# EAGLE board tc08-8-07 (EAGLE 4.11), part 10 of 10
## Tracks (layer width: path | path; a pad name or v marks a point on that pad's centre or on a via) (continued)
WR_EN\  (via drill 0.61) (continued)
  Bottom 0.254: v200.06,123.49 201.65,125.08 | 201.65,125.08 211.81,125.08 | 211.81,125.08 213.08,123.81 213.08,121.27 214.03,121.27 C12.J2 | 201.65,125.08 181.01,125.08 180.06,124.13 C15.H2 | 211.81,125.08 228.64,125.08 229.59,124.13 C11.H2 | v182.28,131.43 178.47,131.43 176.88,133.02 C15.D2 | v233.4,193.03 232.76,192.39 229.27,192.39 v228.64,191.76 | v217.52,210.17 214.35,213.35 212.44,213.35 208.63,217.16 v208.63,217.79 | v204.82,222.87 204.19,223.51 178.47,223.51 175.93,226.05 174.34,226.05 173.39,227 164.82,227 164.5,226.68 v158.47,226.68 | v157.52,141.91 158.47,140.96 165.45,140.96 166.41,140.01 v167.68,140.01
WRITE_ALL  (via drill 0.61)
  Top 0.254: v223.56,176.2 221.97,177.79 221.97,184.77 221.02,185.73 221.02,189.85 B12.F1 | v285.15,148.58 285.47,148.26 285.47,97.46 285.79,97.14 285.79,94.92 285.47,94.6 285.47,48.88 282.93,46.34 282.93,43.49 281.34,41.9 D07.M2 | v241.34,151.43 241.02,151.75 v241.02,172.71 | v268.96,222.87 270.23,224.14 270.23,226.36 269.91,226.68 269.91,229.86 268.64,231.13 A08.S2 | v224.83,211.12 217.84,204.14 v217.84,203.51 | v221.33,200.65 221.97,200.01 221.97,195.57 v222.29,195.25
  Route15 0.254: v261.66,222.24 260.7,222.24 258.8,220.33 v257.21,221.92 | v249.27,217.48 v252.13,220.33
  Bottom 0.254: v223.56,176.2 223.87,175.88 234.99,175.88 235.94,174.93 B11.M1 241.02,174.61 v241.02,172.71 | v285.15,148.58 284.83,148.26 269.59,148.26 268.96,148.89 267.05,148.89 266.74,149.21 243.56,149.21 v241.34,151.43 | v268.96,222.87 267.05,220.97 262.93,220.97 v261.66,222.24 | v257.21,221.92 256.89,222.24 254.35,222.24 252.45,220.33 v252.13,220.33 | v249.27,217.48 250.23,216.52 250.23,211.12 249.27,211.12 248.64,210.49 229.27,210.49 228.64,211.12 v224.83,211.12 | v217.84,203.51 220.7,200.65 v221.33,200.65 | v222.29,195.25 221.33,194.3 221.33,192.39 223.56,192.39 225.14,190.8 225.14,189.54 221.97,189.54 221.33,190.17 B12.F1
WRITE_DATA  (via drill 0.61)
  Top 0.254: v222.6,233.35 222.6,224.78 224.51,222.87 224.51,220.02 225.78,218.74 225.78,210.81 222.6,207.63 222.6,205.41 221.02,203.82 B12.B1 | v279.44,85.71 279.12,85.39 279.12,73.01 279.75,72.38 279.75,67.61 279.12,66.98 279.12,58.72 278.17,57.77 D07.F2 | v235.62,83.49 235.3,83.81 235.3,97.78 232.13,100.95 232.13,124.45 232.45,124.77 232.45,126.03 232.13,126.35 232.13,158.1 231.81,158.42 231.81,160.64 233.08,161.91 233.08,164.45 B11.R1 | v232.76,201.6 232.45,201.28 232.45,197.79 232.13,197.47 232.13,170.17 234.03,168.26 234.03,167.31 235.94,165.4 v235.94,165.09
  Bottom 0.254: v222.6,233.35 222.92,233.67 248,233.67 248.96,234.62 251.81,234.62 A09.R2 | v279.44,85.71 279.12,86.03 252.77,86.03 250.23,83.49 v235.62,83.49 | B12.P1 224.51,167.95 225.46,166.99 230.86,166.99 232.45,165.4 232.76,165.4 B11.R1 v235.94,165.09 | v232.76,201.6 226.73,201.6 225.78,202.55 221.65,202.55 221.33,202.87 B12.B1
WRITE_DATA\  (via drill 0.61)
  Top 0.254: v268.01,139.37 266.74,138.1 266.74,135.24 267.05,134.93 267.05,126.35 v267.37,126.03 | v261.02,113.33 260.7,113.02 260.7,107.62 260.39,107.3 v260.39,104.13 | v269.28,93.65 269.59,93.33 269.59,91.43 268.96,90.79 v268.96,88.25 | v278.17,59.04 v278.17,61.9
  Route2 0.254: v281.02,150.48 281.02,146.36 279.75,145.08 279.75,144.45 v277.53,142.23 | v267.37,126.03 265.47,124.13 265.47,123.49 267.37,121.59 266.42,120.64 v266.42,119.05 | v260.39,104.13 260.39,103.18 269.28,94.28 v269.28,93.65 | v268.96,88.25 268.96,86.98 267.37,85.39 267.37,83.17 267.05,82.86 267.05,82.22 266.74,81.9 266.74,78.09 279.75,65.08 279.44,64.76 279.44,63.17 v278.17,61.9
  Route15 0.254: v281.02,150.48 279.12,152.39 279.12,153.02 275.94,156.2 275.94,162.55 268.64,169.85 268.64,173.98 B08.M2
  Bottom 0.254: v277.53,142.23 276.9,141.59 270.23,141.59 v268.01,139.37 | v266.42,119.05 261.02,113.65 v261.02,113.33 | v278.17,59.04 279.75,57.46 283.56,57.46 D07.F1
WRITE_OK  (via drill 0.61)
  Top 0.254: v151.17,128.89 149.58,130.48 149.58,160.01 v149.9,160.33 | v94.97,160.01 94.97,254.62 89.25,260.34 89.25,264.47 87.67,266.05 A22.D2 87.03,267.32 87.03,269.86 85.76,271.13 v85.76,285.74 | v241.02,200.96 241.02,205.41 240.7,205.73 240.7,211.76 241.34,212.39 v241.34,225.09 | v261.66,227 261.34,227.32 261.34,230.49 260.7,231.13 260.7,240.97 260.39,241.29 v260.39,247 | v277.53,245.73 279.12,245.73 279.12,281.29 v272.45,287.96
  Bottom 0.254: v151.17,128.89 151.8,128.26 153.71,128.26 153.71,124.45 C17.H2 | B15.R1 180.69,165.09 179.42,163.82 178.15,163.82 177.52,163.18 171.49,163.18 168.95,160.64 153.39,160.64 152.75,161.28 150.85,161.28 v149.9,160.33 149.58,160.01 v94.97,160.01 | v241.02,200.96 240.7,200.65 237.53,200.65 237.21,200.33 B11.C1 | v241.34,225.09 241.34,226.68 243.88,226.68 244.19,227 250.54,227 251.5,226.05 254.35,226.05 255.31,227 v261.66,227 | v260.39,247 260.7,246.68 264.2,246.68 265.15,245.73 v277.53,245.73 | v272.45,287.96 270.86,289.55 237.84,289.55 237.21,288.91 218.48,288.91 218.16,289.23 216.25,289.23 215.62,289.86 214.98,289.86 213.71,288.6 212.44,288.6 211.81,287.96 209.27,287.96 208.63,287.32 190.22,287.32 189.58,287.96 185.14,287.96 183.87,286.69 141.96,286.69 141.64,287.01 134.66,287.01 133.07,285.42 86.08,285.42 v85.76,285.74
WRITE_OK+UTS  (via drill 0.61)
  Top 0.254: v157.52,174.3 155.29,172.07 155.29,151.43 155.93,150.8 155.93,139.05 156.56,138.42 156.56,135.88 158.47,133.97 158.47,113.33 160.06,111.75 C17.M1 | B12.D1 221.02,196.2 221.33,195.89 221.33,191.76 221.97,191.12 221.97,185.73 223.87,183.82 B12.K1
  Bottom 0.254: v157.52,174.3 159.1,175.88 196.89,175.88 197.52,176.52 202.92,176.52 205.46,179.06 218.79,179.06 220.38,180.64 223.24,180.64 B12.K1
WRITE_OK\  (via drill 0.61)
  Top 0.254: v149.26,124.77 149.26,122.54 150.53,121.27 C17.J2 | v90.84,113.02 89.25,114.61 89.25,156.2 91.79,158.74 91.79,162.86 v91.16,163.5 | v121.64,164.77 121,165.4 121,187.95 121.32,188.27 121.32,192.71 121,193.03 121,195.25 v122.59,196.84 | v134.66,201.92 135.93,203.19 135.93,205.41 136.24,205.73 v136.24,247.96 | v226.1,256.85 228.95,256.85 228.95,254.62 230.22,253.35 v230.22,252.4
  Route15 0.254: v128.94,113.97 v142.28,127.3 | v177.84,251.13 v183.87,257.16 | v190.54,256.53 190.85,256.53 v192.76,254.62 | v198.79,253.99 199.11,253.99 v204.51,248.59 | v208.95,250.18 209.9,250.18 210.54,249.54 211.81,249.54 220.7,258.43 223.24,255.89 225.14,255.89 v226.1,256.85
  Bottom 0.254: v149.26,124.77 145.77,128.26 143.23,128.26 v142.28,127.3 | v128.94,113.97 127.99,113.02 v90.84,113.02 | v91.16,163.5 91.48,163.18 120.05,163.18 v121.64,164.77 | v122.59,196.84 124.5,198.74 130.85,198.74 134.02,201.92 v134.66,201.92 | v136.24,247.96 137.2,248.91 174.66,248.91 176.88,251.13 v177.84,251.13 | v183.87,257.16 185.14,255.89 187.04,255.89 187.68,256.53 v190.54,256.53 | v192.76,254.62 193.39,255.26 197.52,255.26 v198.79,253.99 | v204.51,248.59 204.82,248.91 207.68,248.91 v208.95,250.18 | v230.22,252.4 231.18,253.35 232.13,253.35 232.76,252.72 241.65,252.72 241.97,252.4 244.19,252.4 245.46,253.67 A10.J1
WRTM  (via drill 0.61)
  Top 0.254: v273.09,55.55 272.77,55.87 272.77,59.36 v271.18,60.95 | v255.94,56.18 254.35,57.77 254.35,61.27 v254.99,61.9 | v249.59,61.9 248,63.49 248,68.88 v249.27,70.16 | v246.42,72.38 245.46,73.33 245.46,81.58 v245.78,81.9 | v227.68,82.54 227.37,82.86 227.37,87.3 228.32,88.25 228.32,90.47 227.37,91.43 v227.37,92.38 | v214.67,104.44 214.67,107.3 C12.N2 | v224.19,201.6 222.92,201.6 222.92,200.96 222.6,200.65 222.6,196.2 223.24,195.57 223.24,194.93 222.29,193.98 v222.29,193.34 | v234.99,167.63 v234.99,171.76 | v248.96,147.31 v248.96,153.66 | C10.K2 v242.92,120.32
  Route2 0.254: v229.91,204.14 227.68,201.92 224.51,201.92 v224.19,201.6 | v256.26,139.37 241.65,124.77 241.65,121.59 v242.92,120.32
  Route15 0.254: v249.27,70.16 248.32,71.11 247.69,71.11 v246.42,72.38 | v227.37,92.38 224.51,95.24 222.92,95.24 220.7,97.46 220.7,98.41 v214.67,104.44 | v222.29,193.34 223.24,192.39 223.56,192.39 225.14,190.8 225.14,190.17 227.68,187.63 227.68,186.99 v226.73,186.04 | v227.05,181.28 227.05,180.33 227.68,179.69 227.68,179.06 v234.99,171.76 | v234.99,167.63 234.99,167.31 236.89,165.4 236.89,164.77 v246.1,155.56 | v248.96,147.31 248.96,146.67 v256.26,139.37
  Bottom 0.254: C12.N2 214.98,108.25 215.94,109.21 231.49,109.21 239.43,117.14 242.29,117.14 C10.K2 | v273.09,55.55 279.12,55.55 280.39,54.28 D07.H2 | v271.18,60.95 270.55,61.58 265.15,61.58 259.43,55.87 256.26,55.87 v255.94,56.18 | v254.99,61.9 254.67,61.58 249.91,61.58 v249.59,61.9 | v245.78,81.9 245.15,82.54 v227.68,82.54 | v229.91,204.14 232.45,206.68 235.94,206.68 B11.A1 | v226.73,186.04 225.78,185.09 225.78,181.92 226.41,181.92 v227.05,181.28 | v246.1,155.56 248,153.66 v248.96,153.66
WRTM+FR03  (via drill 0.61)
  Top 0.254: v218.48,89.21 219.11,89.84 219.11,95.55 219.43,95.87 219.43,108.57 v221.02,110.16 | v267.69,172.39 267.05,173.02 267.05,179.37 268.01,180.33 B08.K2 | v255.31,152.39 254.99,152.07 v254.99,144.77
  Route2 0.254: v267.69,172.39 267.69,172.07 264.83,169.21 264.51,169.21 263.88,168.58 263.88,165.72 257.21,159.05 257.21,158.42 v256.26,157.47 | v254.99,144.77 254.99,144.13 251.18,140.32 251.18,139.69 249.91,138.42 248,138.42 244.83,135.24 244.83,133.97 225.78,114.92 225.78,113.33 224.19,111.75 C12.M1
  Bottom 0.254: v218.48,89.21 218.16,89.52 215.3,89.52 214.98,89.21 C12.V2 | v221.02,110.16 221.65,110.8 223.24,110.8 C12.M1 | v256.26,157.47 256.26,156.83 256.89,156.2 256.89,152.39 v255.31,152.39
WRTM\  (via drill 0.61)
  Top 0.254: v258.48,103.18 260.07,103.18 260.07,97.14 v259.75,96.83 | v264.51,96.83 263.88,96.19 263.88,94.28 265.78,92.38 v265.78,90.47 | v287.06,87.62 287.69,86.98 287.69,85.71 289.91,83.49 289.91,72.06 288.33,70.47 288.33,68.57 v288.01,68.25 | v289.91,65.08 v289.91,67.93 | v243.88,134.93 244.83,133.97 244.83,130.8 v245.46,130.16
  Route2 0.254: v252.45,179.37 253.72,180.64 254.67,179.69 256.26,179.69 258.8,182.23 261.34,182.23 261.97,182.87 261.97,184.14 264.83,186.99 267.69,186.99 B08.H2 | v246.42,179.37 247.37,178.42 247.37,169.21 246.1,167.95 246.1,166.99 247.37,165.72 247.37,163.18 v246.42,162.23 | v253.08,150.8 253.08,148.58 248,143.5 248,140.96 248.96,140.01 248,139.05 247.69,139.05 243.88,135.24 v243.88,134.93
  Route15 0.254: v258.48,103.18 257.85,103.81 255.94,101.91 255.31,101.91 253.08,104.13 252.45,104.13 245.78,110.8 243.56,110.8 C10.M2 | v246.42,179.37 v252.45,179.37 | v246.42,162.23 246.42,160.33 253.72,153.02 253.72,151.43 v253.08,150.8 | v245.46,130.16 245.46,129.53 247.37,127.62 247.37,123.18 248,122.54 248,114.29 v246.42,112.7
  Bottom 0.254: v259.75,96.83 260.07,96.51 264.2,96.51 v264.51,96.83 | v265.78,90.47 266.42,89.84 270.55,89.84 270.86,90.16 272.13,90.16 273.09,89.21 275.63,89.21 277.21,87.62 v287.06,87.62 | v288.01,68.25 288.33,67.93 v289.91,67.93 | v289.91,65.08 288.64,63.81 288.64,59.04 287.69,58.09 287.69,54.6 D07.H1 | v246.42,112.7 245.15,111.43 243.56,111.43 C10.M2
XOR_TO_LPB  (via drill 0.61)
  Top 0.254: 241.65,126.03 241.02,126.67 240.38,126.67 C10.F2 239.75,122.54 238.48,121.27 238.48,96.83 239.43,95.87 C10.T2 239.43,94.6 239.43,92.06 237.21,89.84 237.21,78.09 237.84,77.46 v237.84,36.82 | 241.65,126.03 242.92,126.03 C10.E2 | 241.65,126.03 241.65,100 242.61,99.05 C10.S2
  Bottom 0.254: v237.84,36.82 236.57,36.82 235.94,36.18 219.11,36.18 218.16,35.23 D12.P2
XSA_DY  (via drill 0.61)
  Top 0.254: v146.72,170.49 145.77,169.53 145.77,155.56 146.72,154.61 146.72,146.99 146.4,146.67 146.4,110.48 148.94,107.94 148.94,97.46 150.53,95.87 C17.T2 | v188,173.02 188.31,173.34 188.31,177.47 B14.L2 189.27,178.42 189.27,181.28 190.22,182.23 190.22,188.58 194.03,192.39 194.03,197.47 194.35,197.79 194.35,201.92 194.98,202.55 B14.B1 | v261.66,258.75 261.66,259.7 264.51,262.56 264.51,265.74 264.83,266.05 A08.D2 | v254.04,250.81 v254.04,258.75 | v198.79,241.92 197.2,240.33 197.2,230.81 197.52,230.49 197.52,226.36 197.2,226.05 197.2,214.62 v197.52,214.3 | v192.76,211.44 192.12,210.81 v192.12,208.27
  Route2 0.254: v192.12,208.27 195.93,204.46 195.3,203.82 B14.B1
  Route15 0.254: v228,244.78 226.1,244.78 v224.19,242.87
  Bottom 0.254: v146.72,170.49 148.94,172.71 187.68,172.71 v188,173.02 | v254.04,258.75 v261.66,258.75 | v254.04,250.81 252.13,248.91 249.27,248.91 243.56,243.19 229.59,243.19 v228,244.78 | v224.19,242.87 223.87,243.19 219.43,243.19 219.11,243.51 218.48,243.51 218.16,243.19 208.32,243.19 207.68,243.83 207.05,243.83 205.78,242.56 199.43,242.56 v198.79,241.92 | v197.52,214.3 194.66,211.44 v192.76,211.44
XSAD  (via drill 0.61)
  Top 0.254: v228,237.16 228.32,237.48 228.32,241.92 227.05,243.19 A11.L2 | v258.16,237.16 258.48,236.84 258.48,235.57 A09.R1
  Bottom 0.254: v228,237.16 228.64,236.52 245.15,236.52 246.1,237.48 248,237.48 248.64,236.84 257.85,236.84 v258.16,237.16
XSAD\  (via drill 0.61)
  Top 0.254: v196.89,40.95 198.16,39.68 198.16,37.77 v191.81,31.42 | v189.27,28.88 188.31,27.93 188.31,27.29 v183.87,22.85 | v91.79,23.48 75.92,39.36 v75.92,99.68 | v95.92,100.32 95.6,100.63 95.6,149.85 v96.24,150.48 | v127.04,158.42 126.72,158.74 v126.72,174.93 | v126.4,180.96 126.4,183.18 127.35,184.14 v127.35,189.54
  Route2 0.254: v197.52,44.12 195.93,42.53 195.93,41.9 v196.89,40.95 | v189.27,28.88 v191.81,31.42 | v126.72,174.93 126.72,175.56 128.31,177.15 128.31,179.06 v126.4,180.96 | v154.34,189.54 v179.42,214.62 | v192.76,216.21 192.76,216.84 193.71,217.79 193.71,218.74 221.97,247 224.51,247 226.41,248.91 228,248.91 229.59,250.49 A11.K2
  Bottom 0.254: v197.52,44.12 201.01,44.12 D13.L2 | v183.87,22.85 182.6,21.58 180.69,21.58 180.06,20.94 121,20.94 118.78,23.16 116.88,23.16 116.56,23.48 v91.79,23.48 | v75.92,99.68 76.55,100.32 v95.92,100.32 | v96.24,150.48 100.05,154.29 111.48,154.29 115.29,158.1 117.83,158.1 118.46,157.47 126.08,157.47 v127.04,158.42 | v127.35,189.54 127.67,189.22 154.02,189.22 v154.34,189.54 | v179.42,214.62 191.17,214.62 v192.76,216.21
XSTA  (via drill 0.61)
  Top 0.254: D13.N2 201.97,37.45 204.19,35.23 D13.P2 204.51,35.55 204.51,40.63 D13.M2 | B07.B1 284.52,202.55 284.83,202.24 284.83,198.11 285.47,197.47 285.47,188.9 286.74,187.63 B07.H1 287.06,186.68 285.47,185.09 285.47,175.88 284.2,174.61 B07.N1 283.56,171.12 283.56,167.95 282.93,167.31 282.93,164.14 282.29,163.5 | B07.D2 277.53,196.2 276.58,195.25 276.58,179.37 277.53,178.42 B07.L2 277.53,177.15 276.58,176.2 276.58,159.37 | 276.58,115.88 277.53,114.92 C07.L2 | 276.58,115.88 276.58,128.89 277.85,130.16 C07.D2 277.53,133.97 277.21,134.29 277.21,138.42 276.58,139.05 276.58,159.37 | 282.29,163.5 281.34,162.55 B07.S2 280.39,161.59 278.8,161.59 276.58,159.37 | 283.88,149.53 283.88,149.85 282.29,151.43 282.29,163.5 | 283.88,149.53 283.88,140.32 C07.B1 | 283.88,149.53 285.47,149.53 286.1,148.89 286.1,129.53 287.37,128.26 C07.H1 | v274.36,42.85 275.94,44.44 275.94,71.43 277.21,72.69 277.21,87.62 276.58,88.25 276.58,115.88
  Bottom 0.254: D13.M2 205.14,40.63 208.32,40.63 209.59,39.36 231.81,39.36 232.76,38.4 D11.N1 234.03,38.4 234.99,39.36 244.19,39.36 247.37,42.53 274.04,42.53 v274.36,42.85 | C04.E1 324.84,129.84 323.25,128.26 319.12,128.26 316.58,125.72 305.15,125.72 304.52,125.08 291.5,125.08 290.55,124.13 288.01,124.13 C07.H1
XSTA\  (via drill 0.61)
  Top 0.254: 204.51,50.47 204.51,53.33 D13.H2 204.51,54.6 203.55,55.55 203.55,66.03 203.24,66.35 203.24,68.57 v206.41,71.74 | 204.51,50.47 204.51,48.25 D13.K2 | 204.51,50.47 202.28,50.47 D13.J2 | D16.N2 164.18,38.4 166.41,40.63 D16.M2 | D14.L2 189.58,44.75 191.81,44.75 191.81,46.98 D14.K2 | v266.42,148.26 266.42,159.37 265.15,160.64 B08.R2 | v321.03,148.26 321.03,130.48 321.98,129.53 321.98,127.62 C04.F1 | v254.04,110.48 254.35,110.8 254.35,120.64 v254.67,120.96 | v254.04,127.94 253.08,128.89 253.08,130.8 v254.99,132.7
  Route2 0.254: v221.02,72.06 225.46,76.5 225.46,77.77 228.64,80.95 228.64,81.9 244.19,97.46 244.19,101.59 251.81,109.21 252.77,109.21 v254.04,110.48 | v254.67,120.96 254.67,122.86 252.45,125.08 253.72,126.35 253.72,127.62 v254.04,127.94 | v254.99,132.7 254.99,133.97 263.24,142.23 263.24,145.08 v266.42,148.26
  Bottom 0.254: D16.M2 167.36,41.58 168.31,42.53 183.87,42.53 185.46,44.12 188.31,44.12 D14.L2 | D13.J2 201.01,50.47 199.43,48.88 193.71,48.88 192.76,47.93 D14.K2 | v266.42,148.26 268.64,148.26 269.28,147.62 313.41,147.62 314.04,148.26 v321.03,148.26 | v206.41,71.74 212.44,71.74 213.08,72.38 216.25,72.38 217.21,71.43 220.38,71.43 v221.02,72.06

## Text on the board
Top: 1 | A
Bottom: A
tPlace: 28 | 27 | 26 | 25 | 24 | 23 | 22 | 21 | 20 | 19 | 18 | 17 | 16 | 15 | 14 | 13 | 12 | 11 | 10 | 9 | 8 | 7 | 6 | 5 | 4 | 3 | 2 | 1 | Rip Up NC | Fix G821 connections | Fold in ECOs. | A | B | C | D
bPlace: A | B | C | D | 11 | 28 | 27 | 26 | 25 | 24 | 23 | 22 | 21 | 20 | 19 | 18 | 17 | 16 | 15 | 14 | 13 | 12 | 10 | 9 | 8 | 7 | 6 | 5 | 4 | 3 | 2 | 1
